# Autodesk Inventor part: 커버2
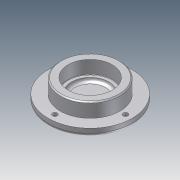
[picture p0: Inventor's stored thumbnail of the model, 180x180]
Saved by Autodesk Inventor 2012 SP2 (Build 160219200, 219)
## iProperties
Company: 한국ATC센터
Created: 2014-10
Part Number: 커버2
Document SubType Name: Modeling
Designer: KYOUNG IL JANG
Density: 1 g/cm^3
Mass: 44.7286 g
Surface Area: 161.165 cm^2
Volume: 44.7286 cm^3
Material: 기본값
Author: KYOUNG IL JANG
Revision Number: 1
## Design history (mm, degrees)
sketch "스케치1"
  geometry: C1 r 38 at (0, 0); 1 further point
  constraints: 1 centre point, 1 coincident
  dimensions: "d0" = 76 diameter of C1
extrude "돌출1" new body sketch "스케치1" distance "d1" = 7; taper "d2" = 0 deg
sketch "스케치2"
  geometry: C1 r 27 at (0, 0); 1 further point
  constraints: 1 centre point, 1 coincident
  dimensions: "d3" = 54 diameter of C1
extrude "돌출2" join sketch "스케치2" distance "d4" = 13; taper "d5" = 0 deg
hole "구멍2" diameter "d20" = 34; stored, may be unused: countersink angle "d24" = 90 deg, drill point angle "d26" = 0 deg; dims "d18" = 10, "d19" = 10, "d21" = 6, "d22" = 40, "d23" = 12, "d25" = 3
fillet "모깎기2" dims "d34" = 3
fillet "모깎기1" dims "d27" = 0.3
chamfer "모따기1" distance "d28" = 1; stored, may be unused: second distance "d29" = 2, angle "d30" = 45 deg
sketch "스케치4" dims "d35" = 64
  geometry: 3 further points
  constraints: 2 horizontal alignment, 1 coincident, 2 other
hole "구멍3" sketch "스케치4" at (32, 0) diameter "d36" = 4.5; stored, may be unused: countersink angle "d40" = 90 deg, drill point angle "d42" = 118 deg; dims "d37" = 6, "d38" = 8, "d39" = 4.4, "d41" = 13
node "솔리드1"
pattern_circular "원형 패턴1" dims angle "d44" = 360 deg
